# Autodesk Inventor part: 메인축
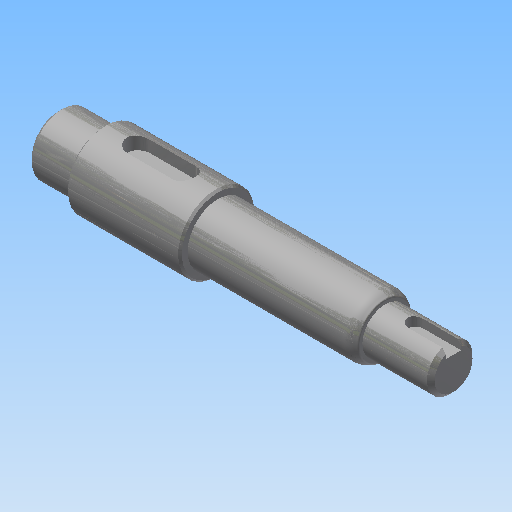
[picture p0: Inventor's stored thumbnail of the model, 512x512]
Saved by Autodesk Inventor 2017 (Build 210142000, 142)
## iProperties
Created: 2019-03
Part Number: 메인축
Material: 강철, 연강
Document SubType Name: Modeling
Designer: mduedu
Density: 1 g/cm^3
Appearance: 강철
Author: mduedu
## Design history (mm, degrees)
sketch "스케치1"
  geometry: L1 (0, 0)-(12, 0); L2 (12, 0)-(12, 8); L3 (12, 8)-(0, 8); L4 (0, 8)-(0, 0); L5 (12, 0)-(42, 0); L6 (42, 0)-(42, 10); L7 (42, 10)-(12, 10); L8 (12, 10)-(12, 0); L9 (42, 0)-(86, 0); L10 (86, 0)-(86, 8); L11 (86, 8)-(42, 8); L12 (42, 8)-(42, 0); L13 (86, 0)-(104, 0); L14 (104, 0)-(104, 6); L15 (104, 6)-(86, 6); L16 (86, 6)-(86, 0)
  constraints: 32 end point, 8 parallel, 4 horizontal, 4 perpendicular
  dimensions: "d0" = 16 diameter of L3 L1; "d2" = 20 diameter of L7 L5; "d3" = 16 diameter of L11 L9; "d4" = 12 diameter of L15 L13; "d5" = 12 distance of L2.end L3.end; "d6" = 30 distance of L6.end L7.end; "d7" = 86 distance between parallel lines of L10 L4; "d8" = 104 distance between parallel lines of L14 L4
revolve "회전1" sketch "스케치1" stored, may be unused: angle "d9" = 90 deg
node "작업 평면1"
sketch "스케치2" dims "d10" = 18
  geometry: L1 (6, -3)-(-6, -3); L2 (-6, -3)-(-6, 3); L3 (-6, 3)-(6, 3); L4 (6, 3)-(6, -3); L5 (15, 10)-(15, -10) reference; 3 further points
  constraints: 8 end point, 2 midpoint, 2 parallel, 2 vertical alignment, 1 horizontal, 1 horizontal alignment, 1 perpendicular, 4 other
  dimensions: "d12" = 6 distance between parallel lines of L3 L1; "d13" = 6 dimension on L5
extrude "돌출1" cut sketch "스케치2" distance "d14" = 3.5; taper "d15" = 0 deg
node "작업 평면2"
sketch "스케치3"
  geometry: L1 (-9, 6)-(-9, -6) reference; L2 (1, -2)-(-9, -2); L3 (1, 2)-(-9, 2); A1 r 2 centre (1, 0) between (1, -2) and (1, 2); 2 further points
  constraints: 4 end point, 2 point on circle, 2 point on line, 2 tangent, 1 centre point, 1 horizontal alignment, 1 midpoint, 1 parallel, 1 perpendicular
  dimensions: "d16" = 12 dimension on A1 L1; "d17" = 4 distance between parallel lines of L3 L2
extrude "돌출2" cut sketch "스케치3" distance "d18" = 2.5; taper "d19" = 0 deg
chamfer "모따기1" distance "d20" = 1; stored, may be unused: second distance "d21" = 2, angle "d22" = 45 deg
chamfer "모따기2" distance "d23" = 0.5; stored, may be unused: second distance "d24" = 2, angle "d25" = 45 deg
chamfer "모따기3" distance "d26" = 1.73; stored, may be unused: second distance "d27" = 2, angle "d28" = 30 deg
fillet "모깎기2" dims "d31" = 0.5, "d32" = 4
node "솔리드1"
